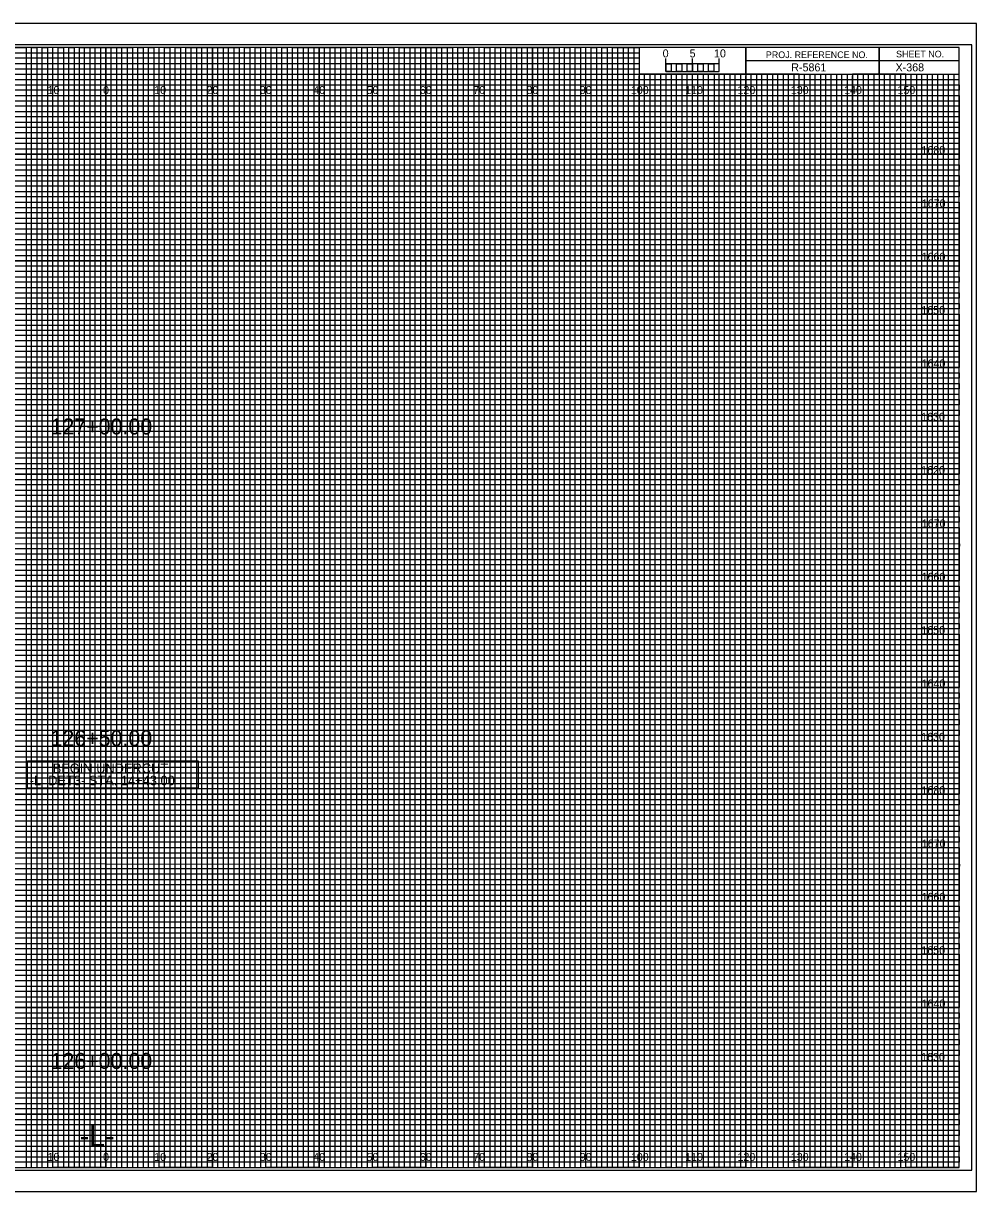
# Model space of a CAD drawing. Extents: x -13 to 323, y -5 to 2414.
# Drawn here: x 144.5 to 323.3, y 875.5 to 1094.5 of the extents above; entities that cross this region are included whole.
import ezdxf

# ---------------------------------------------------------------- set-up
doc = ezdxf.new("R2010")
doc.units = 0
for name, color, linetype in [('Exist XS Center Line Elevation Label', 7, 'Continuous'), ('Prop Grid Mask', 7, 'Continuous'), ('Prop XS Alignment Label', 7, 'Continuous'), ('Prop XS Bar Scale Labels', 7, 'Continuous'), ('Prop XS Elevation Labels', 7, 'Continuous'), ('Prop XS Offset Labels', 7, 'Continuous'), ('Prop XS Project Number', 7, 'Continuous'), ('Prop XS Sheet Number', 7, 'Continuous'), ('Prop XS Station Labels', 7, 'Continuous'), ('Sheet Cross Section CELL', 7, 'Continuous'), ('Sheet Cross Section Grid Major CELL', 7, 'Continuous'), ('Sheet Cross Section Grid Middle CELL', 7, 'Continuous'), ('Sheet Cross Section Grid Minor 1 CELL', 7, 'Continuous'), ('Sheet Cross Section Grid Minor 2 CELL', 7, 'Continuous'), ('Sheet Cross Section Scale CELL', 7, 'Continuous'), ('Sheet Cutting Line CELL', 7, 'Continuous'), ('Sheet DOT Grid CELL', 7, 'Continuous'), ('Sheet Plot Border Inside CELL', 7, 'Continuous'), ('Sheet Plot Border Outside CELL', 7, 'Continuous')]:
    doc.layers.add(name, color=color, linetype=linetype)

msp = doc.modelspace()

# ---------------------------------------------------------------- linework, layer by layer
at = {"layer": 'Prop Grid Mask'}
msp.add_lwpolyline([(145.3, 956.27), (177.29, 956.27), (177.29, 951.14), (145.3, 951.14)], close=True, dxfattribs=at)
at = {"layer": 'Sheet Cross Section CELL'}
for p, q in [((305, 1090), (305, 1085)), ((305, 1085), (305, 1090)), ((280, 1087.5), (280, 1085)), ((320, 1087.49), (280, 1087.49)), ((280, 1085), (320, 1085))]:
    msp.add_line(p, q, dxfattribs=at)
for points in [[(320, 1090), (0, 1090), (0, 880), (320, 880)], [(280, 1090), (260, 1090), (260, 1085.03), (280, 1085.03)], [(320, 1090), (280, 1090), (280, 1085), (320, 1085)]]:
    msp.add_lwpolyline(points, close=True, dxfattribs=at)
at = {"layer": 'Sheet Cross Section Grid Major CELL'}
for p, q in [((150, 1090), (140, 1090)), ((150, 880), (150, 1090)), ((170, 1090), (160, 1090)), ((160, 1090), (160, 880)), ((170, 880), (170, 1090)), ((190, 1090), (180, 1090)), ((180, 1090), (180, 880)), ((190, 880), (190, 1090)), ((210, 1090), (200, 1090)), ((200, 1090), (200, 880)), ((210, 880), (210, 1090)), ((230, 1090), (220, 1090)), ((220, 1090), (220, 880)), ((230, 880), (230, 1090)), ((250, 1090), (240, 1090)), ((240, 1090), (240, 880)), ((250, 880), (250, 1090)), ((260, 1090), (260, 880)), ((270, 880), (270, 1085)), ((290, 1085), (280, 1085)), ((280, 1085), (280, 880)), ((290, 880), (290, 1085)), ((310, 1085), (300, 1085)), ((300, 1085), (300, 880)), ((310, 880), (310, 1085)), ((160, 880), (150, 880)), ((180, 880), (170, 880)), ((200, 880), (190, 880)), ((220, 880), (210, 880)), ((240, 880), (230, 880)), ((260, 880), (250, 880)), ((280, 880), (270, 880)), ((300, 880), (290, 880)), ((320, 880), (310, 880)), ((320, 880), (320, 880))]:
    msp.add_line(p, q, dxfattribs=at)
for points in [[(0, 1080), (320, 1080), (320, 1070), (0, 1070)], [(0, 1060), (320, 1060), (320, 1050), (0, 1050)], [(0, 1040), (320, 1040), (320, 1030), (0, 1030)], [(0, 1020), (320, 1020), (320, 1010), (0, 1010)], [(0, 1000), (320, 1000), (320, 990), (0, 990)], [(0, 980), (320, 980), (320, 970), (0, 970)], [(0, 960), (320, 960), (320, 950), (0, 950)], [(0, 940), (320, 940), (320, 930), (0, 930)], [(0, 920), (320, 920), (320, 910), (0, 910)], [(0, 900), (320, 900), (320, 890), (0, 890)]]:
    msp.add_lwpolyline(points, dxfattribs=at)
at = {"layer": 'Sheet Cross Section Grid Middle CELL'}
for points in [[(135, 1090), (145, 1090), (145, 880), (155, 880), (155, 1090), (165, 1090), (165, 880), (175, 880), (175, 1090), (185, 1090), (185, 880), (195, 880), (195, 1090), (205, 1090), (205, 880), (215, 880), (215, 1090), (225, 1090), (225, 880), (235, 880), (235, 1090), (245, 1090), (245, 880), (255, 880), (255, 1090), (259.93, 1090), (260, 1090), (260, 1085), (264.99, 1085), (264.99, 880), (275, 880), (275, 1085), (285, 1085), (285, 880), (295, 880), (295, 1085), (305, 1085), (305, 880), (315, 880), (315, 1085)], [(0, 1085), (275, 1085)], [(0, 1065), (320, 1065), (320, 1075), (0, 1075)], [(0, 1045), (320, 1045), (320, 1055), (0, 1055)], [(0, 1025), (320, 1025), (320, 1035), (0, 1035)], [(0, 1005), (320, 1005), (320, 1015), (0, 1015)], [(0, 985), (320, 985), (320, 995), (0, 995)], [(0, 965), (320, 965), (320, 975), (0, 975)], [(0, 945), (320, 945), (320, 955), (0, 955)], [(0, 925), (320, 925), (320, 935), (0, 935)], [(0, 905), (320, 905), (320, 915), (0, 915)], [(0, 885), (320, 885), (320, 895), (0, 895)]]:
    msp.add_lwpolyline(points, dxfattribs=at)
at = {"layer": 'Sheet Cross Section Grid Minor 1 CELL'}
for p, q in [((0, 1089), (260, 1089)), ((260, 1089), (260, 1087.98)), ((260, 1087.98), (0, 1087.98)), ((0, 1087), (260, 1087)), ((260, 1087), (260, 1085.89)), ((260, 1085.89), (0, 1085.89)), ((0, 1084), (320, 1084))]:
    msp.add_line(p, q, dxfattribs=at)
for points in [[(0, 1083), (270, 1083), (320, 1083), (320, 1082), (0, 1082)], [(0, 1081), (320, 1081), (320, 1079), (0, 1079)], [(0, 1078), (320, 1078), (320, 1077), (0, 1076.98)], [(0, 1076), (320, 1076), (320, 1074), (0, 1074)], [(0, 1073), (320, 1073), (320, 1072), (0, 1072)], [(0, 1071), (320, 1071), (320, 1069), (0, 1069)], [(0, 1068), (320, 1068), (320, 1067), (0, 1067)], [(0, 1066), (320, 1066), (320, 1064), (0, 1064)], [(0, 1063), (320, 1063), (320, 1062), (0, 1062)], [(0, 1061), (320, 1061), (320, 1059), (0, 1059)], [(0, 1058), (320, 1058), (320, 1057), (0, 1057)], [(0, 1056), (320, 1056), (320, 1053.95), (320, 1053), (320, 1052), (0, 1052)], [(0, 1054), (320, 1054), (320, 1053), (0, 1053)], [(0, 1051), (320, 1051), (320, 1049), (0, 1049.03)], [(0, 1049.03), (320, 1049), (320, 1048), (0, 1048)], [(0, 1047), (320, 1047), (320, 1046), (0, 1046)], [(0, 1044), (320, 1044), (320, 1043), (0, 1043)], [(0, 1042), (320, 1042), (320, 1041), (0, 1041)], [(-0.07, 1038.89), (320, 1038.89), (320, 1037.88), (-0.07, 1037.88)], [(0, 1037), (320, 1037), (320, 1036), (0, 1036)], [(0, 1034), (320, 1034), (320, 1033), (0, 1033)], [(0, 1032), (320, 1032), (320, 1031), (0, 1031)], [(0, 1029), (320, 1029), (320, 1028), (0, 1028)], [(0, 1027), (320, 1027), (320, 1026), (0, 1026)], [(0, 1024), (320, 1024), (320, 1023), (0, 1023)], [(0, 1022), (320, 1022), (320, 1021), (0, 1021)], [(0, 1019), (320, 1019), (319.99, 1017.98), (0, 1018)], [(0, 1017), (320, 1017), (320, 1016), (0, 1016)], [(0, 1014), (320, 1014), (320, 1013), (0, 1013)], [(0, 1012), (320, 1012), (320, 1011), (0, 1011)], [(0, 1009), (320, 1009), (320, 1008), (0, 1008)], [(0, 1007), (320, 1007), (320, 1006), (0, 1006)], [(0, 1004), (320, 1004), (320, 1003), (0, 1003)], [(0, 1002), (320, 1002), (320, 1001), (0, 1001)], [(0, 999), (320, 999), (320, 998), (0, 998)], [(0, 996.99), (320.07, 996.91), (320, 996), (0, 996)], [(0, 994), (320, 994), (320, 993), (0, 993)], [(0, 992), (320, 992), (320, 991), (0, 991)], [(0, 989), (320, 989), (320, 988), (0, 988)], [(0, 987), (320, 987), (320, 986), (0, 986)], [(0, 984), (320, 984), (320, 983), (0, 983)], [(0, 982), (320, 982), (320, 981), (0, 981)], [(0, 979), (320, 979), (320, 978), (0, 978)], [(0, 977), (320, 977), (320, 976), (0, 976)], [(0, 974), (320, 974), (320, 973), (0, 973)], [(0, 972), (320, 972), (320, 971), (0, 971)], [(0, 969), (320, 969), (320, 968), (0, 968)], [(0, 967), (320, 967), (320, 966), (0, 966)], [(0, 964), (320, 964), (320, 963), (0, 963)], [(0, 962), (320, 962), (320, 961), (0, 961)], [(0, 959), (320, 959), (319.99, 957.98), (0, 958)], [(0, 957), (320, 957), (320, 956), (0, 956)], [(0, 954), (320, 954), (320, 953), (0, 953)], [(0, 952), (320, 952), (320, 951), (0, 951)], [(0, 949), (320, 949), (320, 948), (0, 948)], [(0, 947), (320, 947), (320, 946), (0, 946)], [(0, 944), (320, 944), (320, 943), (0, 943)], [(0, 942), (320, 942), (320, 941), (0, 941)], [(0, 939), (320, 939), (320, 938), (0, 938)], [(0, 936.99), (320.07, 936.91), (320, 936), (0, 936)], [(0, 934), (320, 934), (320, 933), (0, 933)], [(0, 932), (320, 932), (320, 931), (0, 931)], [(0, 929), (320, 929), (320, 928), (0, 928)], [(0, 927), (320, 927), (320, 926), (0, 926)], [(0, 924), (320, 924), (320, 923), (0, 923)], [(0, 922), (320, 922), (320, 921), (0, 921)], [(0, 919), (320, 919), (320, 918), (0, 918)], [(0, 917), (320, 917), (320, 916), (0, 916)], [(0, 914), (320, 914), (320, 913), (0, 913)], [(0, 912), (320, 912), (320, 911), (0, 911)], [(0, 909), (320, 909), (320, 908), (0, 908)], [(0, 907), (320, 907), (320, 906), (0, 906)], [(0, 904), (320, 904), (320, 903), (0, 903)], [(0, 902), (320, 902), (320, 901), (0, 901)], [(0, 899), (320, 899), (320, 898), (0, 898)], [(0, 897), (320, 897), (320, 896), (0, 896)], [(0, 894), (320, 894), (320, 893), (0, 893)], [(0, 892), (320, 892), (320, 891), (0, 891)], [(0, 889), (320, 889), (320, 888), (0, 888)], [(0, 887), (320, 887), (320, 886), (0, 886)], [(0, 884), (320, 884), (320, 883), (0, 883)], [(0, 882), (320, 882), (320, 881), (0, 881)]]:
    msp.add_lwpolyline(points, dxfattribs=at)
at = {"layer": 'Sheet Cross Section Grid Minor 2 CELL'}
for p, q in [((267, 1085), (266.01, 1085)), ((266.01, 1085), (266.01, 880)), ((267, 880), (267, 1085)), ((269, 1085), (268, 1085)), ((268, 1085), (268, 880)), ((269, 880), (269, 1085)), ((266.01, 880), (265, 880)), ((268, 880), (267, 880))]:
    msp.add_line(p, q, dxfattribs=at)
for points in [[(145, 880), (146, 880), (146, 1090), (147, 1090), (147, 880)], [(147, 880), (148, 880), (148, 1090), (149, 1090), (149, 880)], [(150, 880), (151, 880), (151, 1090), (152, 1090), (152, 880)], [(152, 880), (153, 880), (153, 1090), (154, 1090), (154, 880)], [(155, 880), (156, 880), (156, 1090), (157, 1090), (157, 880)], [(157, 880), (158, 880), (158, 1090), (159, 1090), (159, 880)], [(160, 880), (161, 880), (161, 1090), (162, 1090), (162, 880)], [(162, 880), (163, 880), (163, 1090), (164, 1090), (164, 880)], [(165, 880), (166, 880), (166, 1090), (167, 1090), (167, 880)], [(167, 880), (168, 880), (168, 1090), (169, 1090), (169, 880)], [(170, 880), (171, 880), (171, 1090), (172, 1090), (172, 880)], [(172, 880), (173, 880), (173, 1090), (174, 1090), (174, 880)], [(175, 880), (176, 880), (176, 1090), (177, 1090), (177, 880)], [(177, 880), (178, 880), (178, 1090), (179, 1090), (179, 880)], [(180, 880), (181, 880), (181, 1090), (182, 1090), (182, 880)], [(182, 880), (183, 880), (183, 1090), (184, 1090), (184, 880)], [(185, 880), (186, 880), (186, 1090), (187, 1090), (187, 880)], [(187, 880), (188, 880), (188, 1090), (189, 1090), (189, 880)], [(190, 880), (191, 880), (191, 1090), (192, 1090), (192, 880)], [(192, 880), (193, 880), (193, 1090), (194, 1090), (194, 880)], [(195, 880), (196, 880), (196, 1090), (197, 1090), (197, 880)], [(197, 880), (198, 880), (198, 1090), (199, 1090), (199, 880)], [(200, 880), (201, 880), (201, 1090), (202, 1090), (202, 880)], [(202, 880), (203, 880), (203, 1090), (204, 1090), (204, 880)], [(205, 880), (206, 880), (206, 1090), (207, 1090), (207, 880)], [(207, 880), (208, 880), (208, 1090), (209, 1090), (209, 880)], [(210, 880), (211, 880), (211, 1090), (212, 1090), (212, 880)], [(212, 880), (213, 880), (213, 1090), (214, 1090), (214, 880)], [(215, 880), (216, 880), (216, 1090), (217, 1090), (217, 880)], [(217, 880), (218, 880), (218, 1090), (219, 1090), (219, 880)], [(220, 880), (221, 880), (221, 1090), (222, 1090), (222, 880)], [(222, 880), (223, 880), (223, 1090), (224, 1090), (224, 880)], [(225, 880), (226, 880), (226, 1090), (227, 1090), (227, 880)], [(227, 880), (228, 880), (228, 1090), (229, 1090), (229, 880)], [(230, 880), (231, 880), (231, 1090), (232, 1090), (232, 880)], [(232, 880), (233, 880), (233, 1090), (234, 1090), (234, 880)], [(235, 880), (236, 880), (236, 1090), (237, 1090), (237, 880)], [(237, 880), (238, 880), (238, 1090), (239, 1090), (239, 880)], [(240, 880), (241, 880), (241, 1090), (242, 1090), (242, 880)], [(242, 880), (243, 880), (243, 1090), (244, 1090), (244, 880)], [(245, 880), (246, 880), (246, 1090), (247, 1090), (247, 880)], [(247, 880), (248, 880), (248, 1090), (249, 1090), (249, 880)], [(250, 880), (251, 880), (251, 1090), (252, 1090), (252, 880)], [(252, 880), (253, 880), (253, 1090), (254, 1090), (254, 880)], [(255, 880), (256, 880), (256, 1090), (257, 1090), (257, 880)], [(257, 880), (258, 880), (258, 1090), (259, 1090), (259, 880)], [(260, 880), (261, 880), (261, 1085), (262.02, 1085), (262.02, 880)], [(262, 880), (263, 880), (263, 1085), (263.99, 1085), (263.99, 880)], [(270, 880), (270.98, 880), (270.98, 1085), (272, 1085), (272, 880)], [(272, 880), (273, 880), (273, 1085), (274.05, 1085), (274.05, 880)], [(275, 880), (276, 880), (276, 1085), (277, 1085), (277, 880)], [(277, 880), (278, 880), (278, 1085), (279, 1085), (279, 880)], [(280, 880), (281, 880), (281, 1085), (282, 1085), (282, 880)], [(282, 880), (283, 880), (283, 1085), (284, 1085), (284, 880)], [(285, 880), (286, 880), (286, 1085), (287, 1085), (287, 880)], [(287, 880), (288, 880), (288, 1085), (289, 1085), (289, 880)], [(290, 880), (291, 880), (291, 1085), (292, 1085), (292, 880)], [(292, 880), (293, 880), (293, 1085), (294, 1085), (294, 880)], [(295, 880), (296, 880), (296, 1085), (297, 1085), (297, 880)], [(297, 880), (298, 880), (298, 1085), (299, 1085), (299, 880)], [(300, 880), (301, 880), (301, 1085), (302, 1085), (302, 880)], [(302, 880), (303, 880), (303, 1085), (304, 1085), (304, 880)], [(305, 880), (306, 880), (306, 1085), (307, 1085), (307, 880)], [(307, 880), (308, 880), (308, 1085), (309, 1085), (309, 880)], [(310, 880), (311, 880), (311, 1085), (312, 1085), (312, 880)], [(312, 880), (313, 880), (313, 1085), (314, 1085), (314, 880)], [(315, 880), (316, 880), (316, 1085), (317, 1085), (317, 880)], [(317, 880), (318, 880), (318, 1085), (319, 1085), (319, 880)]]:
    msp.add_lwpolyline(points, dxfattribs=at)
at = {"layer": 'Sheet Cross Section Scale CELL'}
for p, q in [((265, 1085.49), (265, 1087.9)), ((265, 1086.9), (265, 1087.9)), ((270, 1085.49), (270, 1087.9)), ((275, 1085.49), (275, 1087.9)), ((275, 1086.9), (275, 1087.9))]:
    msp.add_line(p, q, dxfattribs=at)
for points in [[(275, 1086.9), (265, 1086.9), (265, 1085.49), (275, 1085.49)], [(265, 1086.9), (266, 1086.9), (266, 1085.49), (265, 1085.49)], [(267, 1086.9), (268, 1086.9), (268, 1085.49), (267, 1085.49)], [(269, 1086.9), (270, 1086.9), (270, 1085.49), (269, 1085.49)], [(271, 1086.9), (272, 1086.9), (272, 1085.49), (271, 1085.49)], [(273, 1086.9), (274, 1086.9), (274, 1085.49), (273, 1085.49)]]:
    msp.add_lwpolyline(points, close=True, dxfattribs=at)
at = {"layer": 'Sheet Cutting Line CELL'}
for p, q in [((323.3, 1094.5), (-13.4, 1094.5)), ((-13.4, 875.5), (323.3, 875.5))]:
    msp.add_line(p, q, dxfattribs=at)
at = {"layer": 'Sheet DOT Grid CELL'}
for p, q in [((150, 880), (150, 1090)), ((160, 880), (160, 1090)), ((170, 880), (170, 1090)), ((180, 880), (180, 1090)), ((190, 880), (190, 1090)), ((200, 880), (200, 1090)), ((210, 880), (210, 1090)), ((220, 880), (220, 1090)), ((230, 880), (230, 1090)), ((240, 880), (240, 1090)), ((250, 880), (250, 1090)), ((260, 880), (260, 1084.69)), ((270, 880), (270, 1084.69)), ((280, 880), (280, 1084.69)), ((290, 880), (290, 1084.69)), ((300, 880), (300, 1084.69)), ((310, 880), (310, 1084.69)), ((0, 1080), (320, 1080)), ((0, 1070), (320, 1070)), ((0, 1060), (320, 1060)), ((0, 1050), (320, 1050)), ((0, 1040), (320, 1040)), ((0, 1030), (320, 1030)), ((0, 1020), (320, 1020)), ((0, 1010), (320, 1010)), ((0, 1000), (320, 1000)), ((0, 990), (320, 990)), ((0, 980), (320, 980)), ((0, 970), (320, 970)), ((0, 960), (320, 960)), ((0, 950), (320, 950)), ((0, 940), (320, 940)), ((0, 930), (320, 930)), ((0, 920), (320, 920)), ((0, 910), (320, 910)), ((0, 900), (320, 900)), ((0, 890), (320, 890))]:
    msp.add_line(p, q, dxfattribs=at)
at = {"layer": 'Sheet Plot Border Inside CELL'}
msp.add_lwpolyline([(-10.8, 879.5), (322.4, 879.5), (322.4, 1090.5), (-10.8, 1090.5)], close=True, dxfattribs=at)
at = {"layer": 'Sheet Plot Border Outside CELL'}
msp.add_lwpolyline([(-13.4, 875.5), (323.3, 875.5), (323.3, 1094.5), (-13.4, 1094.5)], close=True, dxfattribs=at)

# ---------------------------------------------------------------- texts
at = {"layer": 'Exist XS Center Line Elevation Label'}
for s, p in [('BEGIN UNDERCUT ', (150, 953.95)), ('-L_DET3- STA. 14+43.00', (145.68, 951.67))]:
    msp.add_text(s, height=1.8, dxfattribs=at).set_placement(p)
at = {"layer": 'Prop XS Alignment Label'}
msp.add_text('-L-', height=4, dxfattribs=at).set_placement((155.06, 884))
at = {"layer": 'Prop XS Bar Scale Labels'}
for s, p in [('5', (269.47, 1088.12)), ('10', (274.04, 1088.12))]:
    msp.add_text(s, height=1.5, dxfattribs=at).set_placement(p)
at = {"layer": 'Prop XS Elevation Labels'}
for s, p in [('1680', (312.95, 1070)), ('1670', (313, 1060)), ('1660', (312.97, 1050)), ('1650', (312.92, 1040)), ('1640', (312.97, 1030)), ('1630', (312.89, 1020)), ('1620', (312.9, 1010)), ('1670', (313, 1000)), ('1660', (312.97, 990)), ('1650', (312.92, 980)), ('1640', (312.97, 970)), ('1630', (312.89, 960)), ('1680', (312.95, 950)), ('1670', (313, 940)), ('1660', (312.97, 930)), ('1650', (312.92, 920)), ('1640', (312.97, 910)), ('1630', (312.89, 900))]:
    msp.add_text(s, height=1.5, dxfattribs=at).set_placement(p)
at = {"layer": 'Prop XS Offset Labels'}
for s, p in [('10', (149.04, 1081.25)), ('0', (159.45, 1081.25)), ('0', (159.45, 1081.25)), ('10', (169.04, 1081.25)), ('20', (178.86, 1081.25)), ('30', (188.86, 1081.25)), ('40', (198.86, 1081.25)), ('50', (208.86, 1081.25)), ('60', (218.86, 1081.25)), ('70', (228.86, 1081.25)), ('80', (238.86, 1081.25)), ('90', (248.86, 1081.25)), ('100', (258.44, 1081.25)), ('110', (268.62, 1081.25)), ('120', (278.44, 1081.25)), ('130', (288.44, 1081.25)), ('140', (298.44, 1081.25)), ('150', (308.44, 1081.25)), ('10', (149.04, 881.25)), ('0', (159.45, 881.25)), ('0', (159.45, 881.25)), ('10', (169.04, 881.25)), ('20', (178.86, 881.25)), ('30', (188.86, 881.25)), ('40', (198.86, 881.25)), ('50', (208.86, 881.25)), ('60', (218.86, 881.25)), ('70', (228.86, 881.25)), ('80', (238.86, 881.25)), ('90', (248.86, 881.25)), ('100', (258.44, 881.25)), ('110', (268.62, 881.25)), ('120', (278.44, 881.25)), ('130', (288.44, 881.25)), ('140', (298.44, 881.25)), ('150', (308.44, 881.25))]:
    msp.add_text(s, height=1.5, dxfattribs=at).set_placement(p)
at = {"layer": 'Prop XS Project Number'}
msp.add_text('R-5861', height=1.5, dxfattribs=at).set_placement((288.53, 1085.5))
at = {"layer": 'Prop XS Sheet Number'}
msp.add_text('X-368', height=1.5, dxfattribs=at).set_placement((308.09, 1085.5))
at = {"layer": 'Prop XS Station Labels'}
for s, p in [('127+00.00', (149.59, 1017.44)), ('126+50.00', (149.59, 959.01)), ('126+00.00', (149.59, 898.5))]:
    msp.add_text(s, height=3, dxfattribs=at).set_placement(p)
at = {"layer": 'Sheet Cross Section CELL'}
for s, p in [('PROJ. REFERENCE NO.', (283.77, 1087.99)), ('SHEET NO.', (308.19, 1088.12))]:
    msp.add_text(s, height=1.25, dxfattribs=at).set_placement(p)
at = {"layer": 'Sheet Cross Section Scale CELL'}
msp.add_text('0', height=1.5, dxfattribs=at).set_placement((264.41, 1088.12))

doc.saveas('drawing.dxf')
